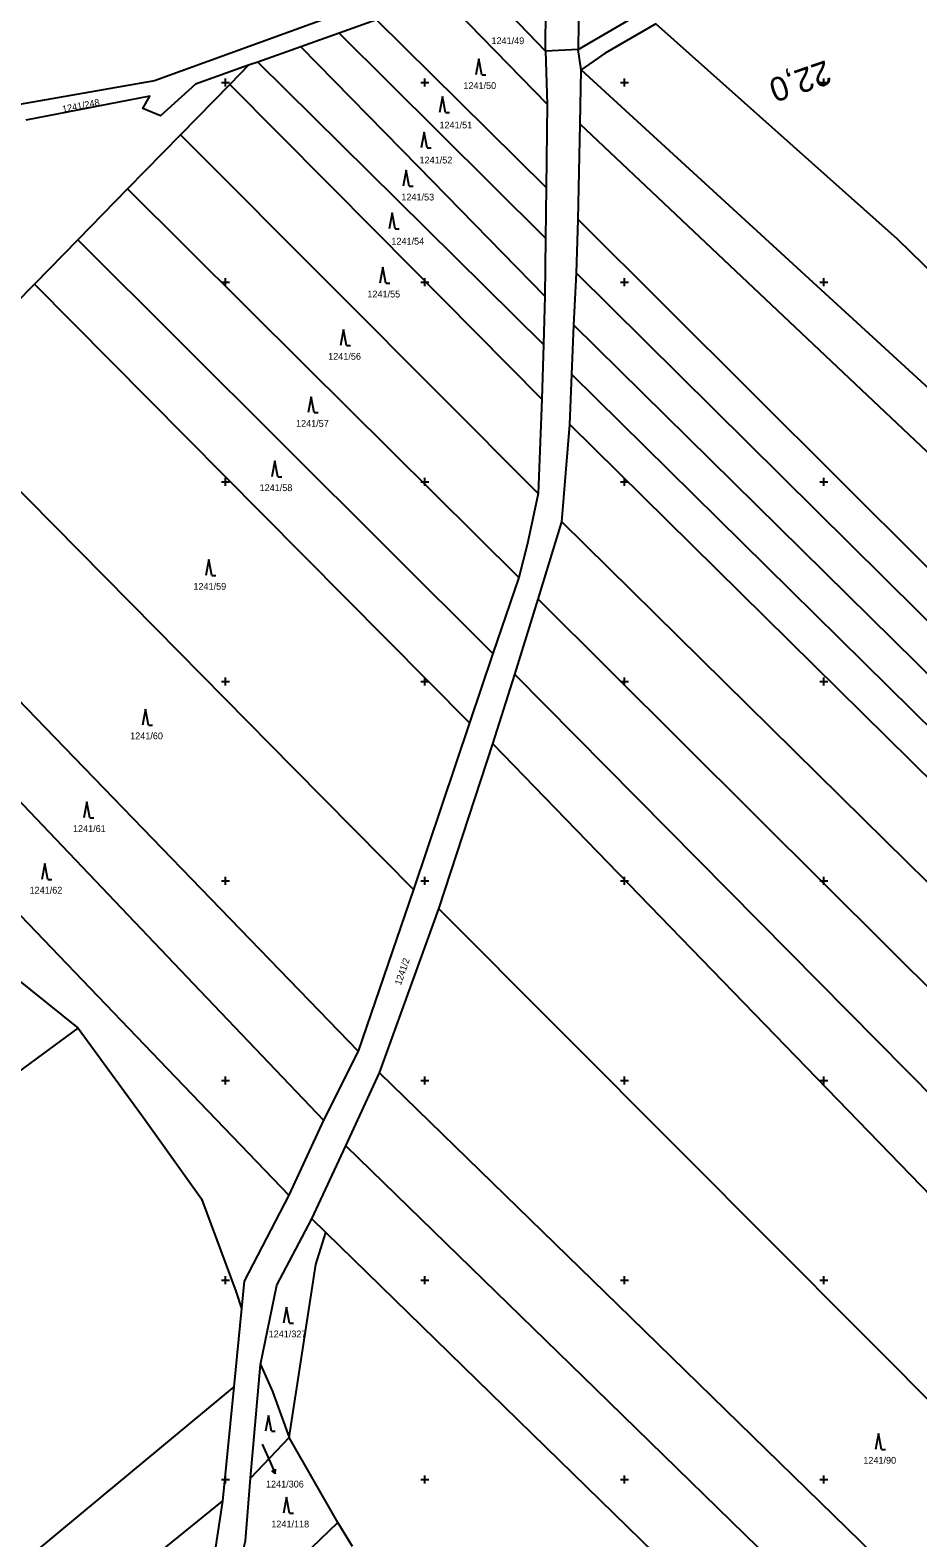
# Model space of a CAD drawing. Extents: x -776734 to -748832, y -1118122 to -976986.
# Drawn here: x -751749 to -751526.4, y -1115264.6 to -1114886.9 of the extents above; entities that cross this region are included whole.
import ezdxf

# ---------------------------------------------------------------- set-up
doc = ezdxf.new("R2010")
doc.units = 0
for name, color, linetype in [('KM_Hranice parcel', 7, 'Continuous'), ('KM_Parcelní čísla', 7, 'Continuous'), ('KM_Pop  PČ popisy', 7, 'Continuous'), ('KM_Značky kultur', 7, 'Continuous'), ('Level 61 Křížky', 7, 'Continuous'), ('SŽG Vrstva 7', 7, 'Continuous')]:
    doc.layers.add(name, color=color, linetype=linetype)

msp = doc.modelspace()

# ---------------------------------------------------------------- linework, layer by layer
at = {"layer": 'KM_Hranice parcel'}
for p, q in [((-751611.22, -1114866.19), (-751611.61, -1114891.73)), ((-751619.8, -1114892.13), (-751636.13, -1114875.06)), ((-751645.58, -1114878.41), (-751619.39, -1114905.36)), ((-751619.8, -1114892.13), (-751619.71, -1114880.94)), ((-751662.15, -1114884.29), (-751671.53, -1114887.62)), ((-751611.61, -1114891.73), (-751594.4, -1114881.65)), ((-751671.53, -1114887.62), (-751681.12, -1114891.02)), ((-751681.12, -1114891.02), (-751691.86, -1114894.83)), ((-751611.61, -1114891.73), (-751619.8, -1114892.13)), ((-751619.8, -1114892.13), (-751619.39, -1114905.36)), ((-751610.82, -1114896.82), (-751611.61, -1114891.73)), ((-751694.2, -1114895.66), (-751698.87, -1114900.43)), ((-751691.86, -1114894.83), (-751694.2, -1114895.66)), ((-751611.09, -1114910.41), (-751610.82, -1114896.82)), ((-751698.87, -1114900.43), (-751711.24, -1114913.05)), ((-751619.39, -1114905.36), (-751619.64, -1114926.27)), ((-751611.54, -1114934.25), (-751611.09, -1114910.41)), ((-751711.24, -1114913.05), (-751724.55, -1114926.64)), ((-751724.55, -1114926.64), (-751737.01, -1114939.35)), ((-751619.64, -1114926.27), (-751619.8, -1114938.96)), ((-751611.99, -1114947.76), (-751611.54, -1114934.25)), ((-751737.01, -1114939.35), (-751747.89, -1114950.46)), ((-751619.8, -1114938.96), (-751619.97, -1114953.48)), ((-751612.64, -1114960.72), (-751611.99, -1114947.76)), ((-751747.89, -1114950.46), (-751775.23, -1114978.37)), ((-751619.97, -1114953.48), (-751620.28, -1114965.58)), ((-751613.13, -1114973.12), (-751612.64, -1114960.72)), ((-751620.28, -1114965.58), (-751620.68, -1114979.27)), ((-751613.63, -1114985.63), (-751613.13, -1114973.12)), ((-751620.68, -1114979.27), (-751621.6, -1115002.97)), ((-751615.7, -1115010.07), (-751613.63, -1114985.63)), ((-751621.58, -1115029.44), (-751615.7, -1115010.07)), ((-751626.49, -1115024.01), (-751632.94, -1115043.01)), ((-751627.48, -1115048.25), (-751621.58, -1115029.44)), ((-751632.94, -1115043.01), (-751638.82, -1115060.35)), ((-751632.94, -1115065.66), (-751627.48, -1115048.25)), ((-751638.82, -1115060.35), (-751652.82, -1115102.17)), ((-751646.49, -1115106.97), (-751632.94, -1115065.66)), ((-751652.82, -1115102.17), (-751666.74, -1115142.61)), ((-751661.35, -1115148.11), (-751646.49, -1115106.97)), ((-751752.68, -1115124.23), (-751736.94, -1115136.91)), ((-751666.74, -1115142.61), (-751675.46, -1115159.97)), ((-751669.82, -1115166.34), (-751661.35, -1115148.11)), ((-751675.46, -1115159.97), (-751684.11, -1115178.76)), ((-751678.35, -1115184.67), (-751669.82, -1115166.34)), ((-751674.84, -1115188.09), (-751678.35, -1115184.67)), ((-751695.96, -1115207.1), (-751697.9, -1115226.76)), ((-751693.71, -1115249.59), (-751691.19, -1115221.19)), ((-751697.9, -1115226.76), (-751700.74, -1115255.4)), ((-751684.06, -1115239.48), (-751693.71, -1115249.59)), ((-751671.87, -1115260.75), (-751684.06, -1115239.48)), ((-751700.75, -1115288.37), (-751671.87, -1115260.75)), ((-751668.19, -1115266.74), (-751671.87, -1115260.75))]:
    msp.add_line(p, q, dxfattribs=at)
for points in [[(-751619.58, -1114864.94), (-751671.94, -1114882.94), (-751717.81, -1114899.58), (-751754.97, -1114906.02), (-751784.43, -1114907.15), (-751843.55, -1114904.34), (-751858.89, -1114907.41)], [(-751662.15, -1114884.29), (-751641.5, -1114904.68), (-751619.64, -1114926.27)], [(-751671.53, -1114887.62), (-751646.45, -1114912.51), (-751619.8, -1114938.96)], [(-751592.08, -1114885.24), (-751604.82, -1114892.62), (-751610.82, -1114896.82)], [(-751276.03, -1115181.12), (-751348.6, -1115110.66), (-751424.62, -1115039.17), (-751470.64, -1114998.48), (-751498.76, -1114971.09), (-751531.53, -1114939.21), (-751592.08, -1114885.24)], [(-751681.12, -1114891.02), (-751651.8, -1114920.96), (-751619.97, -1114953.48)], [(-751694.2, -1114895.66), (-751707.54, -1114900.39), (-751716.28, -1114908.3), (-751720.75, -1114906.52), (-751718.97, -1114903.41), (-751750.07, -1114909.36)], [(-751691.86, -1114894.83), (-751657.04, -1114929.24), (-751620.28, -1114965.58)], [(-751610.82, -1114896.82), (-751491.63, -1115005.97), (-751441.62, -1115052.92), (-751364.11, -1115125.69), (-751286.63, -1115198.43)], [(-751698.87, -1114900.43), (-751662.2, -1114937.4), (-751620.68, -1114979.27)], [(-751292.41, -1115211.12), (-751373.31, -1115134.79), (-751451.65, -1115060.86), (-751495.59, -1115019.4), (-751611.09, -1114910.41)], [(-751711.24, -1114913.05), (-751671.82, -1114952.59), (-751621.6, -1115002.97)], [(-751724.55, -1114926.64), (-751680.02, -1114970.85), (-751626.49, -1115024.01)], [(-751611.54, -1114934.25), (-751502.55, -1115042.84), (-751469.94, -1115075.32), (-751384.97, -1115159.96), (-751310.44, -1115234.21)], [(-751737.01, -1114939.35), (-751685.69, -1114990.47), (-751632.94, -1115043.01)], [(-751315.64, -1115240.86), (-751387.64, -1115169.64), (-751473.51, -1115084.72), (-751508.95, -1115049.67), (-751611.99, -1114947.76)], [(-751747.89, -1114950.46), (-751690.76, -1115008.02), (-751638.82, -1115060.35)], [(-751321.27, -1115247.86), (-751390.42, -1115179.72), (-751474.79, -1115096.57), (-751515.39, -1115056.55), (-751612.64, -1114960.72)], [(-751327.12, -1115255.1), (-751392.5, -1115190.64), (-751476.05, -1115108.27), (-751521.69, -1115063.28), (-751613.13, -1114973.12)], [(-751775.23, -1114978.37), (-751717.58, -1115036.67), (-751682.94, -1115071.71), (-751652.82, -1115102.17)], [(-751333.03, -1115262.42), (-751393.33, -1115202.94), (-751477.33, -1115120.08), (-751528.04, -1115070.06), (-751613.63, -1114985.63)], [(-751800.61, -1115004.27), (-751745.16, -1115061.58), (-751698.78, -1115109.5), (-751666.74, -1115142.61)], [(-751621.6, -1115002.97), (-751624.24, -1115015.43), (-751626.49, -1115024.01)], [(-751344.61, -1115276.77), (-751394.97, -1115227.23), (-751480.94, -1115142.65), (-751539.94, -1115084.61), (-751615.7, -1115010.07)], [(-751812.42, -1115016.33), (-751759.07, -1115072.28), (-751706.35, -1115127.57), (-751675.46, -1115159.97)], [(-751826.42, -1115030.62), (-751774.79, -1115084.37), (-751714.53, -1115147.09), (-751684.11, -1115178.76)], [(-751356.99, -1115292.44), (-751403.05, -1115246.66), (-751490.29, -1115159.94), (-751549.32, -1115101.27), (-751621.58, -1115029.44)], [(-751368.11, -1115310.4), (-751418.59, -1115259.37), (-751499.72, -1115177.37), (-751558.64, -1115117.82), (-751627.48, -1115048.25)], [(-751378.65, -1115327.98), (-751433.41, -1115271.49), (-751504.7, -1115197.94), (-751567.36, -1115133.3), (-751632.94, -1115065.66)], [(-751396.88, -1115357.36), (-751455.66, -1115298.4), (-751517.85, -1115236.02), (-751585.93, -1115167.72), (-751646.49, -1115106.97)], [(-751879.71, -1115241.63), (-751837.58, -1115210.73), (-751780.06, -1115168.54), (-751736.94, -1115136.91)], [(-751736.94, -1115136.91), (-751720.61, -1115159.22), (-751705.99, -1115179.66), (-751697.43, -1115202.74), (-751695.96, -1115207.1)], [(-751661.35, -1115148.11), (-751601.74, -1115206.16), (-751534.09, -1115272.02), (-751481.49, -1115323.24), (-751413.91, -1115389.05)], [(-751669.82, -1115166.34), (-751607.26, -1115227.27), (-751542.69, -1115290.14), (-751499.9, -1115331.82), (-751421.37, -1115408.28)], [(-751684.11, -1115178.76), (-751695.28, -1115200.25), (-751695.96, -1115207.1)], [(-751691.19, -1115221.19), (-751687.13, -1115201.26), (-751678.35, -1115184.67)], [(-751684.06, -1115239.48), (-751677.31, -1115196.13), (-751674.84, -1115188.09)], [(-751433.56, -1115423.29), (-751518.5, -1115340.49), (-751551.38, -1115308.44), (-751612.82, -1115248.55), (-751674.84, -1115188.09)], [(-751691.19, -1115221.19), (-751688.24, -1115227.91), (-751684.06, -1115239.48)], [(-751697.9, -1115226.76), (-751731.21, -1115254.39), (-751799.51, -1115311.05), (-751835.29, -1115340.73)], [(-751700.75, -1115288.37), (-751694.99, -1115265.33), (-751693.71, -1115249.59)], [(-751825.07, -1115356.13), (-751789.36, -1115327.19), (-751716.62, -1115268.27), (-751700.74, -1115255.4)], [(-751700.74, -1115255.4), (-751702.63, -1115267.99), (-751709.62, -1115296.92)]]:
    msp.add_lwpolyline(points, dxfattribs=at)
at = {"layer": 'KM_Pop  PČ popisy'}
for p, q in [((-751690.82, -1115241.11), (-751688.73, -1115245.79)), ((-751688.73, -1115245.79), (-751687.509, -1115248.532)), ((-751687.509, -1115248.532), (-751688.374, -1115247.82)), ((-751687.509, -1115248.532), (-751687.459, -1115247.413))]:
    msp.add_line(p, q, dxfattribs=at)
at = {"layer": 'KM_Značky kultur'}
for p, q in [((-751636.5, -1114894.04), (-751637.25, -1114898.04)), ((-751635.75, -1114898.04), (-751636.5, -1114894.04)), ((-751635.75, -1114898.04), (-751634.754, -1114898.04)), ((-751645.59, -1114903.51), (-751646.34, -1114907.51)), ((-751644.84, -1114907.51), (-751645.59, -1114903.51)), ((-751644.84, -1114907.51), (-751643.844, -1114907.51)), ((-751650.19, -1114912.37), (-751650.94, -1114916.37)), ((-751649.44, -1114916.37), (-751650.19, -1114912.37)), ((-751649.44, -1114916.37), (-751648.444, -1114916.37)), ((-751654.68, -1114921.94), (-751655.43, -1114925.94)), ((-751653.93, -1114925.94), (-751654.68, -1114921.94)), ((-751653.93, -1114925.94), (-751652.934, -1114925.94)), ((-751658.18, -1114932.61), (-751658.93, -1114936.61)), ((-751657.43, -1114936.61), (-751658.18, -1114932.61)), ((-751657.43, -1114936.61), (-751656.434, -1114936.61)), ((-751660.54, -1114946.27), (-751661.29, -1114950.27)), ((-751659.79, -1114950.27), (-751660.54, -1114946.27)), ((-751659.79, -1114950.27), (-751658.794, -1114950.27)), ((-751670.41, -1114961.87), (-751671.16, -1114965.87)), ((-751669.66, -1114965.87), (-751670.41, -1114961.87)), ((-751669.66, -1114965.87), (-751668.664, -1114965.87)), ((-751678.51, -1114978.68), (-751679.26, -1114982.68)), ((-751677.76, -1114982.68), (-751678.51, -1114978.68)), ((-751677.76, -1114982.68), (-751676.764, -1114982.68)), ((-751687.59, -1114994.79), (-751688.34, -1114998.79)), ((-751686.84, -1114998.79), (-751687.59, -1114994.79)), ((-751686.84, -1114998.79), (-751685.844, -1114998.79)), ((-751704.19, -1115019.5), (-751704.94, -1115023.5)), ((-751703.44, -1115023.5), (-751704.19, -1115019.5)), ((-751703.44, -1115023.5), (-751702.444, -1115023.5)), ((-751720.07, -1115056.96), (-751720.82, -1115060.96)), ((-751719.32, -1115060.96), (-751720.07, -1115056.96)), ((-751719.32, -1115060.96), (-751718.324, -1115060.96)), ((-751734.74, -1115080.19), (-751735.49, -1115084.19)), ((-751733.99, -1115084.19), (-751734.74, -1115080.19)), ((-751733.99, -1115084.19), (-751732.994, -1115084.19)), ((-751745.25, -1115095.62), (-751746, -1115099.62)), ((-751744.5, -1115099.62), (-751745.25, -1115095.62)), ((-751744.5, -1115099.62), (-751743.504, -1115099.62)), ((-751684.67, -1115206.79), (-751685.42, -1115210.79)), ((-751683.92, -1115210.79), (-751684.67, -1115206.79)), ((-751683.92, -1115210.79), (-751682.924, -1115210.79)), ((-751689.25, -1115233.89), (-751690, -1115237.89)), ((-751688.5, -1115237.89), (-751689.25, -1115233.89)), ((-751688.5, -1115237.89), (-751687.504, -1115237.89)), ((-751536.27, -1115238.45), (-751537.02, -1115242.45)), ((-751535.52, -1115242.45), (-751536.27, -1115238.45)), ((-751535.52, -1115242.45), (-751534.524, -1115242.45)), ((-751684.7, -1115254.42), (-751685.45, -1115258.42)), ((-751683.95, -1115258.42), (-751684.7, -1115254.42)), ((-751683.95, -1115258.42), (-751682.954, -1115258.42))]:
    msp.add_line(p, q, dxfattribs=at)
at = {"layer": 'Level 61 Křížky'}
for p, q in [((-751701, -1114900), (-751699, -1114900)), ((-751700, -1114900), (-751700, -1114899)), ((-751700, -1114901), (-751700, -1114900)), ((-751651, -1114900), (-751649, -1114900)), ((-751650, -1114900), (-751650, -1114899)), ((-751650, -1114901), (-751650, -1114900)), ((-751601, -1114900), (-751599, -1114900)), ((-751600, -1114900), (-751600, -1114899)), ((-751600, -1114901), (-751600, -1114900)), ((-751551, -1114900), (-751549, -1114900)), ((-751550, -1114900), (-751550, -1114899)), ((-751550, -1114901), (-751550, -1114900)), ((-751700, -1114950), (-751700, -1114949)), ((-751650, -1114950), (-751650, -1114949)), ((-751600, -1114950), (-751600, -1114949)), ((-751550, -1114950), (-751550, -1114949)), ((-751701, -1114950), (-751699, -1114950)), ((-751700, -1114951), (-751700, -1114950)), ((-751651, -1114950), (-751649, -1114950)), ((-751650, -1114951), (-751650, -1114950)), ((-751601, -1114950), (-751599, -1114950)), ((-751600, -1114951), (-751600, -1114950)), ((-751551, -1114950), (-751549, -1114950)), ((-751550, -1114951), (-751550, -1114950)), ((-751701, -1115000), (-751699, -1115000)), ((-751700, -1115000), (-751700, -1114999)), ((-751700, -1115001), (-751700, -1115000)), ((-751651, -1115000), (-751649, -1115000)), ((-751650, -1115000), (-751650, -1114999)), ((-751650, -1115001), (-751650, -1115000)), ((-751601, -1115000), (-751599, -1115000)), ((-751600, -1115000), (-751600, -1114999)), ((-751600, -1115001), (-751600, -1115000)), ((-751551, -1115000), (-751549, -1115000)), ((-751550, -1115000), (-751550, -1114999)), ((-751550, -1115001), (-751550, -1115000)), ((-751701, -1115050), (-751699, -1115050)), ((-751700, -1115050), (-751700, -1115049)), ((-751700, -1115051), (-751700, -1115050)), ((-751651, -1115050), (-751649, -1115050)), ((-751650, -1115050), (-751650, -1115049)), ((-751650, -1115051), (-751650, -1115050)), ((-751601, -1115050), (-751599, -1115050)), ((-751600, -1115050), (-751600, -1115049)), ((-751600, -1115051), (-751600, -1115050)), ((-751551, -1115050), (-751549, -1115050)), ((-751550, -1115050), (-751550, -1115049)), ((-751550, -1115051), (-751550, -1115050)), ((-751701, -1115100), (-751699, -1115100)), ((-751700, -1115100), (-751700, -1115099)), ((-751700, -1115101), (-751700, -1115100)), ((-751651, -1115100), (-751649, -1115100)), ((-751650, -1115100), (-751650, -1115099)), ((-751650, -1115101), (-751650, -1115100)), ((-751601, -1115100), (-751599, -1115100)), ((-751600, -1115100), (-751600, -1115099)), ((-751600, -1115101), (-751600, -1115100)), ((-751551, -1115100), (-751549, -1115100)), ((-751550, -1115100), (-751550, -1115099)), ((-751550, -1115101), (-751550, -1115100)), ((-751700, -1115150), (-751700, -1115149)), ((-751650, -1115150), (-751650, -1115149)), ((-751600, -1115150), (-751600, -1115149)), ((-751550, -1115150), (-751550, -1115149)), ((-751701, -1115150), (-751699, -1115150)), ((-751700, -1115151), (-751700, -1115150)), ((-751651, -1115150), (-751649, -1115150)), ((-751650, -1115151), (-751650, -1115150)), ((-751601, -1115150), (-751599, -1115150)), ((-751600, -1115151), (-751600, -1115150)), ((-751551, -1115150), (-751549, -1115150)), ((-751550, -1115151), (-751550, -1115150)), ((-751701, -1115200), (-751699, -1115200)), ((-751700, -1115200), (-751700, -1115199)), ((-751700, -1115201), (-751700, -1115200)), ((-751651, -1115200), (-751649, -1115200)), ((-751650, -1115200), (-751650, -1115199)), ((-751650, -1115201), (-751650, -1115200)), ((-751601, -1115200), (-751599, -1115200)), ((-751600, -1115200), (-751600, -1115199)), ((-751600, -1115201), (-751600, -1115200)), ((-751551, -1115200), (-751549, -1115200)), ((-751550, -1115200), (-751550, -1115199)), ((-751550, -1115201), (-751550, -1115200)), ((-751701, -1115250), (-751699, -1115250)), ((-751700, -1115250), (-751700, -1115249)), ((-751700, -1115251), (-751700, -1115250)), ((-751651, -1115250), (-751649, -1115250)), ((-751650, -1115250), (-751650, -1115249)), ((-751650, -1115251), (-751650, -1115250)), ((-751601, -1115250), (-751599, -1115250)), ((-751600, -1115250), (-751600, -1115249)), ((-751600, -1115251), (-751600, -1115250)), ((-751551, -1115250), (-751549, -1115250)), ((-751550, -1115250), (-751550, -1115249)), ((-751550, -1115251), (-751550, -1115250))]:
    msp.add_line(p, q, dxfattribs=at)

# ---------------------------------------------------------------- texts
at = {"layer": 'KM_Parcelní čísla'}
for s, p in [('1241/49', (-751633.32, -1114890.35)), ('1241/50', (-751640.36, -1114901.59)), ('1241/51', (-751646.36, -1114911.47)), ('1241/52', (-751651.35, -1114920.25)), ('1241/53', (-751655.91, -1114929.52)), ('1241/54', (-751658.4, -1114940.58)), ('1241/55', (-751664.42, -1114953.82)), ('1241/56', (-751674.25, -1114969.42)), ('1241/57', (-751682.31, -1114986.23)), ('1241/58', (-751691.45, -1115002.34)), ('1241/59', (-751708.03, -1115027.05)), ('1241/60', (-751723.89, -1115064.51)), ('1241/61', (-751738.23, -1115087.74)), ('1241/62', (-751749.11, -1115103.17)), ('1241/327', (-751689.18, -1115214.34)), ('1241/90', (-751540.09, -1115246)), ('1241/306', (-751689.84, -1115251.968)), ('1241/118', (-751688.51, -1115261.97))]:
    msp.add_text(s, height=1.7, dxfattribs=at).set_placement(p)
for s, rotation, p in [('1241/248', 10.999997, (-751740.747, -1114907.484)), ('1241/2', 71, (-751656.016, -1115126.256))]:
    msp.add_text(s, height=1.7, rotation=rotation, dxfattribs=at).set_placement(p)
at = {"layer": 'SŽG Vrstva 7'}
msp.add_text('22,0', height=6, rotation=199.025979, dxfattribs=at).set_placement((-751549.4721, -1114894.2926))

doc.saveas('drawing.dxf')
